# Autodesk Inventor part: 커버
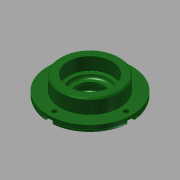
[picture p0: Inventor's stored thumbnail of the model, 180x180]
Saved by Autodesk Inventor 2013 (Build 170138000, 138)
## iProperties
Company: 한국ATC센터
Created: 2016-04
Part Number: 커버
Document SubType Name: Modeling
Designer: mdu
Density: 7.86 g/cm^3
Mass: 351.567 g
Surface Area: 161.165 cm^2
Volume: 44.7286 cm^3
Material: 강철, 연강
Author: mdu
Revision Number: 1
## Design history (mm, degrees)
sketch "스케치1"
  geometry: C1 r 38 at (0, 0); 1 further point
  constraints: 1 centre point, 1 coincident
  dimensions: "d0" = 76 diameter of C1
extrude "돌출1" new body sketch "스케치1" distance "d1" = 7; taper "d2" = 0 deg
sketch "스케치2"
  geometry: C1 r 27 at (0, 0); 1 further point
  constraints: 1 centre point, 1 coincident
  dimensions: "d3" = 54 diameter of C1
extrude "돌출2" join sketch "스케치2" distance "d4" = 13; taper "d5" = 0 deg
sketch "스케치3"
  geometry: C1 r 20 at (0, 0); 1 further point
  constraints: 1 centre point, 1 coincident
  dimensions: "d6" = 40 diameter of C1
extrude "돌출3" join sketch "스케치3" distance "d7" = 5; taper "d8" = 0 deg
hole "구멍1" diameter "d11" = 25; stored, may be unused: countersink angle "d15" = 90 deg, drill point angle "d17" = 118 deg; dims "d9" = 10, "d10" = 10, "d12" = 6, "d13" = 32, "d14" = 8.3, "d16" = 8
hole "구멍2" diameter "d20" = 34; stored, may be unused: countersink angle "d24" = 90 deg, drill point angle "d26" = 0 deg; dims "d18" = 10, "d19" = 10, "d21" = 6, "d22" = 40, "d23" = 12, "d25" = 3
fillet "모깎기2" dims "d34" = 3
fillet "모깎기1" dims "d27" = 0.3
chamfer "모따기1" distance "d28" = 1; stored, may be unused: second distance "d29" = 2, angle "d30" = 45 deg
chamfer "모따기2" distance "d31" = 1.2; stored, may be unused: second distance "d32" = 2, angle "d33" = 30 deg
sketch "스케치4" dims "d35" = 65
  geometry: 3 further points
  constraints: 2 horizontal alignment, 1 coincident, 2 other
hole "구멍3" sketch "스케치4" at (32.5, 0) diameter "d36" = 4.5; stored, may be unused: countersink angle "d40" = 90 deg, drill point angle "d42" = 118 deg; dims "d37" = 6, "d38" = 8, "d39" = 4.4, "d41" = 13
sketch "스케치5"
  geometry: L1 (0, 4)-(5.5, 4); L2 (5.5, 4)-(5.5, -4); L3 (5.5, -4)-(0, -4); L4 (0, -4)-(0, 4); C1 r 2.25 at (0, 0) reference; C2 r 38 at (-32.5, 0) reference; 2 further points
  constraints: 8 end point, 3 horizontal, 2 parallel, 1 perpendicular, 1 tangent, 1 vertical alignment, 1 other
extrude "돌출4" cut sketch "스케치5" stored distance "d47" = 24.5; taper "d48" = 0 deg
node "솔리드1"
pattern_circular "원형 패턴1" dims angle "d44" = 360 deg
pattern_circular "원형 패턴2" dims angle "d50" = 360 deg
node "투영된 루프1"
